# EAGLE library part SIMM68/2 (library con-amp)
AMP connector
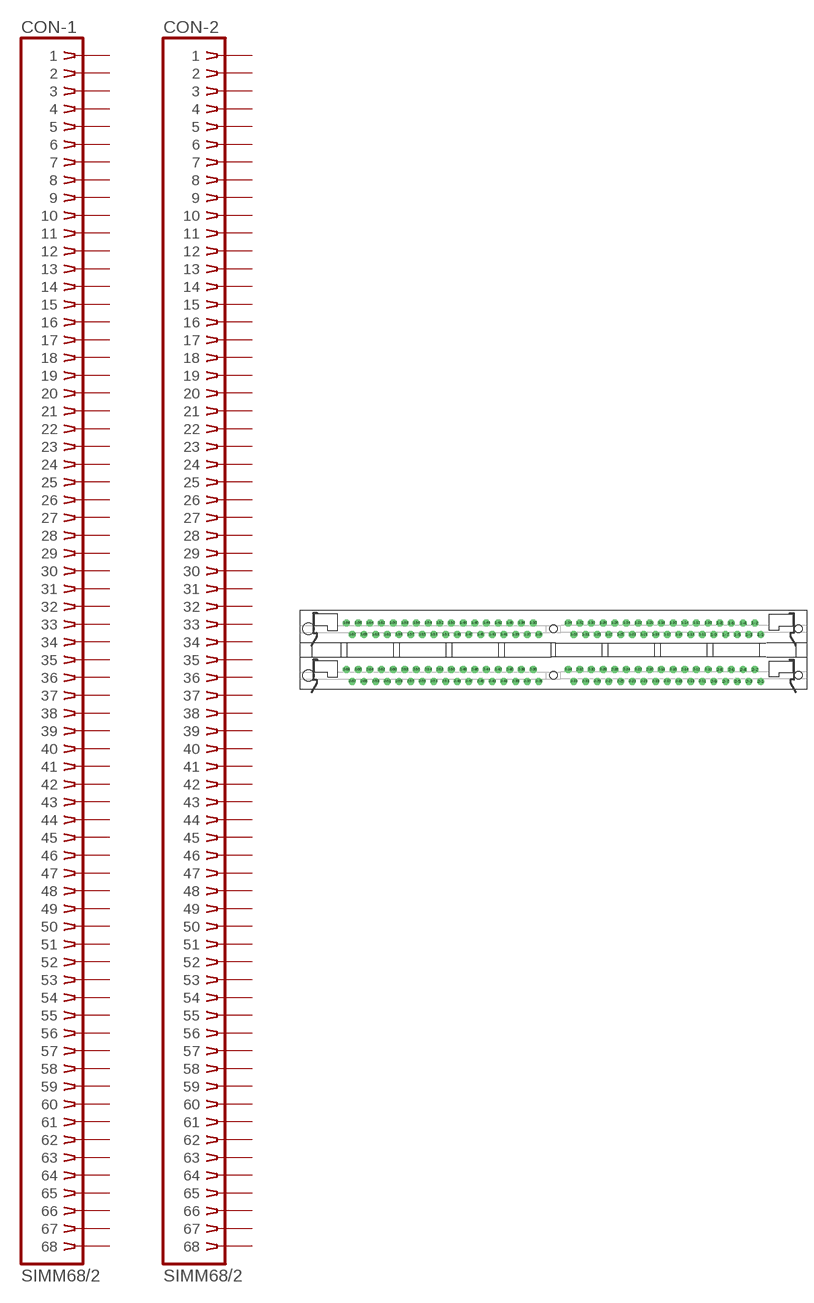
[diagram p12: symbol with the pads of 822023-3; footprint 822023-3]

Designator prefix CON; gates -1=SIMM68 -2=SIMM68

## SIMM68/2 (OC_FARNELL: unknown; OC_NEWARK: unknown)  [822023-3]
1-1  -1:1  pas
1-2  -1:2  pas
1-3  -1:3  pas
1-4  -1:4  pas
1-5  -1:5  pas
1-6  -1:6  pas
1-7  -1:7  pas
1-8  -1:8  pas
1-9  -1:9  pas
1-10  -1:10  pas
1-11  -1:11  pas
1-12  -1:12  pas
1-13  -1:13  pas
1-14  -1:14  pas
1-15  -1:15  pas
1-16  -1:16  pas
1-17  -1:17  pas
1-18  -1:18  pas
1-19  -1:19  pas
1-20  -1:20  pas
1-21  -1:21  pas
1-22  -1:22  pas
1-23  -1:23  pas
1-24  -1:24  pas
1-25  -1:25  pas
1-26  -1:26  pas
1-27  -1:27  pas
1-28  -1:28  pas
1-29  -1:29  pas
1-30  -1:30  pas
1-31  -1:31  pas
1-32  -1:32  pas
1-33  -1:33  pas
1-34  -1:34  pas
1-35  -1:35  pas
1-36  -1:36  pas
1-37  -1:37  pas
1-38  -1:38  pas
1-39  -1:39  pas
1-40  -1:40  pas
1-41  -1:41  pas
1-42  -1:42  pas
1-43  -1:43  pas
1-44  -1:44  pas
1-45  -1:45  pas
1-46  -1:46  pas
1-47  -1:47  pas
1-48  -1:48  pas
1-49  -1:49  pas
1-50  -1:50  pas
1-51  -1:51  pas
1-52  -1:52  pas
1-53  -1:53  pas
1-54  -1:54  pas
1-55  -1:55  pas
1-56  -1:56  pas
1-57  -1:57  pas
1-58  -1:58  pas
1-59  -1:59  pas
1-60  -1:60  pas
1-61  -1:61  pas
1-62  -1:62  pas
1-63  -1:63  pas
1-64  -1:64  pas
1-65  -1:65  pas
1-66  -1:66  pas
1-67  -1:67  pas
1-68  -1:68  pas
2-1  -2:1  pas
2-2  -2:2  pas
2-3  -2:3  pas
2-4  -2:4  pas
2-5  -2:5  pas
2-6  -2:6  pas
2-7  -2:7  pas
2-8  -2:8  pas
2-9  -2:9  pas
2-10  -2:10  pas
2-11  -2:11  pas
2-12  -2:12  pas
2-13  -2:13  pas
2-14  -2:14  pas
2-15  -2:15  pas
2-16  -2:16  pas
2-17  -2:17  pas
2-18  -2:18  pas
2-19  -2:19  pas
2-20  -2:20  pas
2-21  -2:21  pas
2-22  -2:22  pas
2-23  -2:23  pas
2-24  -2:24  pas
2-25  -2:25  pas
2-26  -2:26  pas
2-27  -2:27  pas
2-28  -2:28  pas
2-29  -2:29  pas
2-30  -2:30  pas
2-31  -2:31  pas
2-32  -2:32  pas
2-33  -2:33  pas
2-34  -2:34  pas
2-35  -2:35  pas
2-36  -2:36  pas
2-37  -2:37  pas
2-38  -2:38  pas
2-39  -2:39  pas
2-40  -2:40  pas
2-41  -2:41  pas
2-42  -2:42  pas
2-43  -2:43  pas
2-44  -2:44  pas
2-45  -2:45  pas
2-46  -2:46  pas
2-47  -2:47  pas
2-48  -2:48  pas
2-49  -2:49  pas
2-50  -2:50  pas
2-51  -2:51  pas
2-52  -2:52  pas
2-53  -2:53  pas
2-54  -2:54  pas
2-55  -2:55  pas
2-56  -2:56  pas
2-57  -2:57  pas
2-58  -2:58  pas
2-59  -2:59  pas
2-60  -2:60  pas
2-61  -2:61  pas
2-62  -2:62  pas
2-63  -2:63  pas
2-64  -2:64  pas
2-65  -2:65  pas
2-66  -2:66  pas
2-67  -2:67  pas
2-68  -2:68  pas

## Footprint 822023-3 (pad centres in mm)
SIMM Socket
drill 1.016 round: 1-1 45.085,-1.27; 2-1 45.085,-11.43
drill 1.016 octagon: 1-2 43.815,1.27; 1-3 42.545,-1.27; 1-4 41.275,1.27; 1-5 40.005,-1.27; 1-6 38.735,1.27; 1-7 37.465,-1.27; 1-8 36.195,1.27; 1-9 34.925,-1.27; 1-10 33.655,1.27; 1-11 32.385,-1.27; 1-12 31.115,1.27; 1-13 29.845,-1.27; 1-14 28.575,1.27; 1-15 27.305,-1.27; 1-16 26.035,1.27; 1-17 24.765,-1.27; 1-18 23.495,1.27; 1-19 22.225,-1.27; 1-20 20.955,1.27; 1-21 19.685,-1.27; 1-22 18.415,1.27; 1-23 17.145,-1.27; 1-24 15.875,1.27; 1-25 14.605,-1.27; 1-26 13.335,1.27; 1-27 12.065,-1.27; 1-28 10.795,1.27; 1-29 9.525,-1.27; 1-30 8.255,1.27; 1-31 6.985,-1.27; 1-32 5.715,1.27; 1-33 4.445,-1.27; 1-34 3.175,1.27; 1-35 -3.175,-1.27; 1-36 -4.445,1.27; 1-37 -5.715,-1.27; 1-38 -6.985,1.27; 1-39 -8.255,-1.27; 1-40 -9.525,1.27; 1-41 -10.795,-1.27; 1-42 -12.065,1.27; 1-43 -13.335,-1.27; 1-44 -14.605,1.27; 1-45 -15.875,-1.27; 1-46 -17.145,1.27; 1-47 -18.415,-1.27; 1-48 -19.685,1.27; 1-49 -20.955,-1.27; 1-50 -22.225,1.27; 1-51 -23.495,-1.27; 1-52 -24.765,1.27; 1-53 -26.035,-1.27; 1-54 -27.305,1.27; 1-55 -28.575,-1.27; 1-56 -29.845,1.27; 1-57 -31.115,-1.27; 1-58 -32.385,1.27; 1-59 -33.655,-1.27; 1-60 -34.925,1.27; 1-61 -36.195,-1.27; 1-62 -37.465,1.27; 1-63 -38.735,-1.27; 1-64 -40.005,1.27; 1-65 -41.275,-1.27; 1-66 -42.545,1.27; 1-67 -43.815,-1.27; 1-68 -45.085,1.27; 2-2 43.815,-8.89; 2-3 42.545,-11.43; 2-4 41.275,-8.89; 2-5 40.005,-11.43; 2-6 38.735,-8.89; 2-7 37.465,-11.43; 2-8 36.195,-8.89; 2-9 34.925,-11.43; 2-10 33.655,-8.89; 2-11 32.385,-11.43; 2-12 31.115,-8.89; 2-13 29.845,-11.43; 2-14 28.575,-8.89; 2-15 27.305,-11.43; 2-16 26.035,-8.89; 2-17 24.765,-11.43; 2-18 23.495,-8.89; 2-19 22.225,-11.43; 2-20 20.955,-8.89; 2-21 19.685,-11.43; 2-22 18.415,-8.89; 2-23 17.145,-11.43; 2-24 15.875,-8.89; 2-25 14.605,-11.43; 2-26 13.335,-8.89; 2-27 12.065,-11.43; 2-28 10.795,-8.89; 2-29 9.525,-11.43; 2-30 8.255,-8.89; 2-31 6.985,-11.43; 2-32 5.715,-8.89; 2-33 4.445,-11.43; 2-34 3.175,-8.89; 2-35 -3.175,-11.43; 2-36 -4.445,-8.89; 2-37 -5.715,-11.43; 2-38 -6.985,-8.89; 2-39 -8.255,-11.43; 2-40 -9.525,-8.89; 2-41 -10.795,-11.43; 2-42 -12.065,-8.89; 2-43 -13.335,-11.43; 2-44 -14.605,-8.89; 2-45 -15.875,-11.43; 2-46 -17.145,-8.89; 2-47 -18.415,-11.43; 2-48 -19.685,-8.89; 2-49 -20.955,-11.43; 2-50 -22.225,-8.89; 2-51 -23.495,-11.43; 2-52 -24.765,-8.89; 2-53 -26.035,-11.43; 2-54 -27.305,-8.89; 2-55 -28.575,-11.43; 2-56 -29.845,-8.89; 2-57 -31.115,-11.43; 2-58 -32.385,-8.89; 2-59 -33.655,-11.43; 2-60 -34.925,-8.89; 2-61 -36.195,-11.43; 2-62 -37.465,-8.89; 2-63 -38.735,-11.43; 2-64 -40.005,-8.89; 2-65 -41.275,-11.43; 2-66 -42.545,-8.89; 2-67 -43.815,-11.43; 2-68 -45.085,-8.89
hole 2.438 at -53.34,0
hole 1.626 at 53.34,0
hole 2.438 at -53.34,-10.16
hole 1.626 at 53.34,-10.16
hole 1.626 at 0,0
hole 1.626 at 0,-10.16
